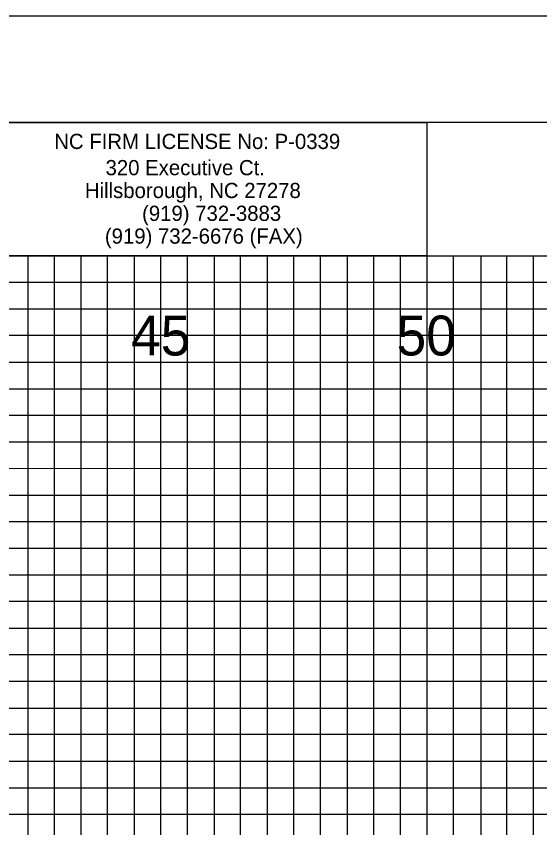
# Model space of a CAD drawing. Extents: x -7 to 162, y -2 to 217.
# Drawn here: x 122.28 to 132.12, y 201.75 to 217 of the extents above; entities that cross this region are included whole.
import ezdxf

# ---------------------------------------------------------------- set-up
doc = ezdxf.new("R2010")
doc.units = 0
for name, color, linetype in [('Exist Cross Section Cell', 7, 'Continuous'), ('Prop CMT Pvmt Course 2', 7, 'Continuous'), ('Prop CMT Pvmt Course 2 Wedge', 7, 'Continuous'), ('Prop CMT Pvmt Course 3', 7, 'Continuous'), ('Prop CMT Pvmt Surface', 7, 'Continuous'), ('Prop CMT Shld Paved Course 1', 7, 'Continuous'), ('Prop CMT Shld Paved Course 2', 7, 'Continuous'), ('Prop CMT Shld Paved Course 3', 7, 'Continuous'), ('Prop CMT Subgrade Earthwork', 7, 'Continuous'), ('Scratch_Level_3', 7, 'Continuous')]:
    doc.layers.add(name, color=color, linetype=linetype)

msp = doc.modelspace()

# ---------------------------------------------------------------- linework, layer by layer
at = {"layer": 'Prop CMT Pvmt Course 2'}
for p, q in [((130, 214.5), (130, 213.99)), ((130, 213.5), (130, 212.945)), ((0, 212), (160, 212))]:
    msp.add_line(p, q, dxfattribs=at)
for points in [[(0, 211.5), (135, 211.5), (160, 211.5)], [(160, 211), (0, 211)], [(0, 210.5), (160, 210.5)], [(160, 209.5), (0, 209.5)], [(0, 209), (160, 209)], [(160, 208.5), (0, 208.49)], [(0, 208), (160, 208)], [(160, 207), (0, 207)], [(0, 206.5), (160, 206.5), (160, 206), (0, 206)], [(0, 205.5), (160, 205.5), (160, 204.5), (0, 204.5)], [(0, 204), (160, 204), (160, 203.5), (0, 203.5)], [(0, 203), (160, 203), (160, 202), (0, 202)]]:
    msp.add_lwpolyline(points, dxfattribs=at)
at = {"layer": 'Prop CMT Pvmt Course 3'}
for p, q in [((125, 215), (120, 215)), ((130, 215), (130, 110)), ((125, 110), (125, 212.5))]:
    msp.add_line(p, q, dxfattribs=at)
for points in [[(160, 212.5), (160, 205), (0, 205)], [(0, 210), (160, 210)]]:
    msp.add_lwpolyline(points, dxfattribs=at)
at = {"layer": 'Prop CMT Pvmt Surface'}
msp.add_lwpolyline([(110.951, 215), (130, 215), (130, 212.5), (110.951, 212.5)], close=True, dxfattribs=at)
at = {"layer": 'Prop CMT Shld Paved Course 1'}
msp.add_lwpolyline([(-6.7, 107.5), (161.65, 107.5), (161.65, 217), (-6.7, 217)], close=True, dxfattribs=at)
at = {"layer": 'Prop CMT Shld Paved Course 2'}
msp.add_lwpolyline([(-5.4, 109.5), (161.2, 109.5), (161.2, 215), (-5.4, 215)], close=True, dxfattribs=at)
at = {"layer": 'Prop CMT Shld Paved Course 3'}
for points in [[(117.5, 215), (122.5, 215)], [(127.5, 215), (129.965, 215), (130, 215), (130, 212.5), (132.495, 212.5), (132.495, 110), (137.5, 110), (137.5, 212.5), (140, 212.5)], [(0, 212.5), (137.5, 212.5)], [(0, 202.5), (160, 202.5), (160, 212.5)], [(122.5, 212.5), (122.5, 110), (127.5, 110), (127.5, 212.5)], [(160, 207.5), (0, 207.5)]]:
    msp.add_lwpolyline(points, dxfattribs=at)
at = {"layer": 'Prop CMT Subgrade Earthwork'}
for points in [[(123, 215), (123.5, 215)], [(124, 215), (124.5, 215)], [(125.5, 215), (126, 215)], [(126.5, 215), (127, 215)], [(128, 215), (128.5, 215)], [(129, 215), (129.5, 215)], [(122.5, 110), (123, 110), (123, 212.5)], [(123.5, 212.5), (123.5, 110)], [(123.5, 110), (124, 110), (124, 212.5)], [(124.5, 212.5), (124.5, 110)], [(125, 110), (125.5, 110), (125.5, 212.5)], [(126, 212.5), (126, 110)], [(126, 110), (126.5, 110), (126.5, 212.5)], [(127, 212.5), (127, 110)], [(127.5, 110), (128, 110), (128, 212.5)], [(128.5, 212.5), (128.5, 110)], [(128.5, 110), (129, 110), (129, 212.5)], [(129.5, 212.5), (129.5, 110)], [(130, 110), (130.5, 110), (130.5, 212.5), (131.01, 212.5), (131.01, 110)], [(131, 110), (131.5, 110), (131.5, 212.5), (131.995, 212.5), (131.995, 110)]]:
    msp.add_lwpolyline(points, dxfattribs=at)
at = {"layer": 'Scratch_Level_3'}
for points in [[(160, 215), (0, 215), (0, 110), (160, 110)], [(140, 215), (130, 215), (130, 212.5), (140, 212.5)]]:
    msp.add_lwpolyline(points, close=True, dxfattribs=at)

# ---------------------------------------------------------------- texts
at = {"layer": 'Exist Cross Section Cell'}
for s, p in [('45', (124.441, 210.625)), ('50', (129.429, 210.625))]:
    msp.add_text(s, height=0.75, dxfattribs=at).set_placement(p)
at = {"layer": 'Prop CMT Pvmt Course 2 Wedge'}
for s, p in [('NC FIRM LICENSE No: P-0339', (122.998, 214.505)), ('320 Executive Ct.', (123.962, 214.012)), ('Hillsborough, NC 27278', (123.573, 213.583)), ('(919) 732-3883', (124.648, 213.154)), ('(919) 732-6676 (FAX)', (123.949, 212.726))]:
    msp.add_text(s, height=0.28573, rotation=360, dxfattribs=at).set_placement(p)

doc.saveas('drawing.dxf')
